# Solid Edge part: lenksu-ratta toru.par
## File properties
Title: lenksu-ratta toru
Author: Stella-Marii
Template: iso metric part.par
Last saved by: Stella-Marii
Revision: 6
Application: Solid Edge
Document Number: 24
Density: 7833,000 kg/m^3
Accuracy: 0,990
Username: Stella-Marii
Material: Steel, structural
Face Style: Steel
Fill Style: ANSI32(Steel)
Virtual Style: Brushed steel
Grouping: Metals\Steel
LibraryName: Materials
Coef. of Thermal Exp: 1.3e-05
Thermal Conductivity: 32.0
Specific Heat: 481.0
Modulus of Elasticity: 199947953000.0
Poisson's Ratio: 0.29
Yield Stress: 262000766.0
Ultimate Stress: 358527364.0
Elongation: 0.0
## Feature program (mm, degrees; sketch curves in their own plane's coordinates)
sketch for "ExtrudedProtrusion_1" plane through (0, 0, 0) normal (0, 0, 1) x-axis (1, 0, 0)
  circle centre (0, 0) radius 22.5
extrude "ExtrudedProtrusion_1" add finite 900 along +normal  FiniteDepth2 = 100 mm
thinwall "Thinwall_1"  Thickness = 3 mm
sketch for "ExtrudedCutout_2" plane through (0, 0, 0) normal (0, 0, 1) x-axis (1, 0, 0)
  line (-12.5, 18.7083) -> (12.5, 18.7083)
  line (12.5, 18.7083) -> (12.5, 26.883)
  line (12.5, 26.883) -> (-12.5, 26.883)
  line (-12.5, 26.883) -> (-12.5, 18.7083)
  dimension (linear) = 12.5
extrude "ExtrudedCutout_2" cut finite 90 along +normal
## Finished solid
Body 1: solid body, 8 faces, 16 edges, 8 vertices.
  Faces by surface: plane 6, cylinder 2
  Edges by curve: circle 8, line 8
Bounding box of the edges (mm): 45.000 x 45.000 x 1000.000, from (-22.5, -22.5, -100) to (22.5, 22.5, 900).
Cylindrical faces by radius (mm): R19.5 x1, R22.5 x1
Planar faces by outward normal: +y 2, +z 2, -z 2
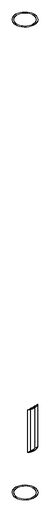
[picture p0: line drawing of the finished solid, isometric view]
